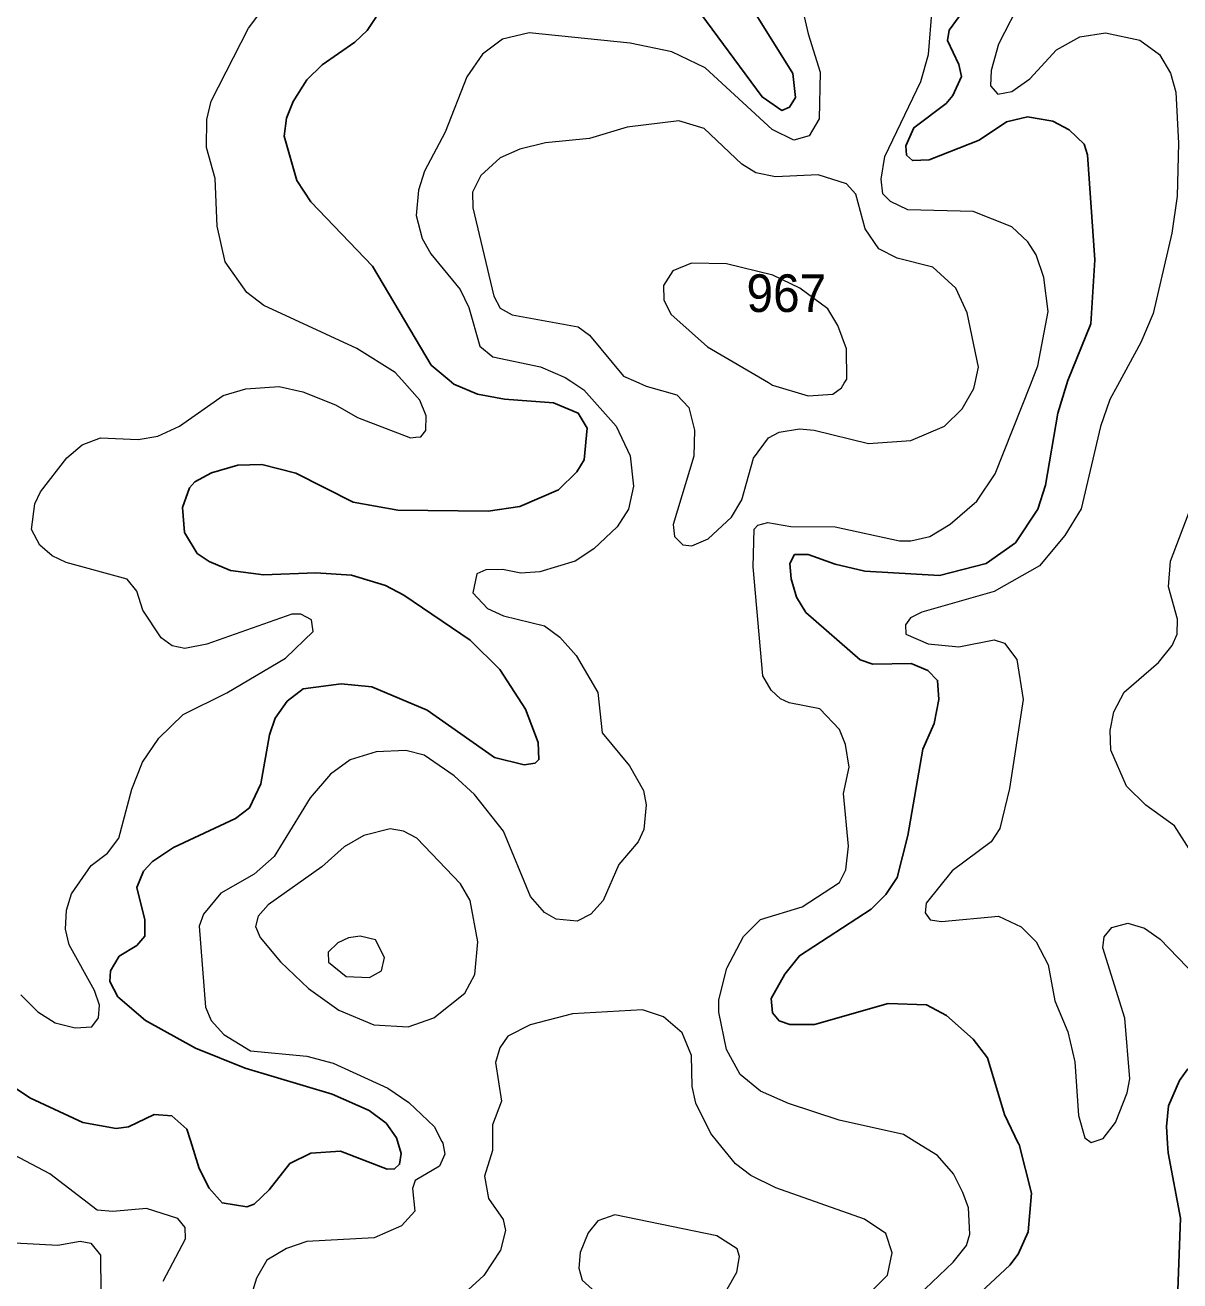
# Model space of a CAD drawing. Extents: x 473.9 to 500, y 7733.1 to 7760.8.
# Drawn here: x 476.742 to 479.198, y 7746.08 to 7748.751 of the extents above; entities that cross this region are included whole.
import ezdxf

# ---------------------------------------------------------------- set-up
doc = ezdxf.new("R2010")
doc.units = 0
doc.header["$LTSCALE"] = 0.032
doc.layers.add('1', color=7, linetype='Continuous', lineweight=25)
doc.layers.add('2', color=7, linetype='Continuous', lineweight=13)
doc.layers.add('21', color=7, linetype='Continuous')

msp = doc.modelspace()

# ---------------------------------------------------------------- linework, layer by layer
at = {"layer": '1'}
for points in [[(477.5474, 7747.5383), (477.5084, 7747.5589), (477.4357, 7747.5809), (477.3604, 7747.5858), (477.2492, 7747.5818), (477.1784, 7747.5908), (477.1331, 7747.61), (477.1081, 7747.6274), (477.0809, 7747.6718), (477.0769, 7747.7251), (477.0912, 7747.7667), (477.103, 7747.7795), (477.1386, 7747.799), (477.1942, 7747.8152), (477.2453, 7747.8166), (477.3178, 7747.7977), (477.4393, 7747.736), (477.5349, 7747.7193), (477.7267, 7747.7169), (477.7937, 7747.7271), (477.876, 7747.7625), (477.9153, 7747.8008), (477.9312, 7747.8267), (477.9375, 7747.8938), (477.9184, 7747.9259), (477.8653, 7747.9478), (477.7612, 7747.9556), (477.7043, 7747.9663), (477.6534, 7747.9876), (477.6436, 7747.9958), (477.6053, 7748.0281), (477.4807, 7748.2382), (477.3496, 7748.3751), (477.3197, 7748.4205), (477.293, 7748.5147), (477.2979, 7748.5535), (477.3118, 7748.5889), (477.3413, 7748.6347), (477.3739, 7748.6669), (477.4432, 7748.7147), (477.4697, 7748.7397), (477.5418, 7748.8495)], [(478.1666, 7748.7915), (478.3092, 7748.5985), (478.3511, 7748.5697), (478.3674, 7748.5764), (478.3805, 7748.5972), (478.3749, 7748.6481), (478.2948, 7748.7769)], [(478.7282, 7748.7695), (478.7069, 7748.7402), (478.7035, 7748.7189), (478.7279, 7748.6674), (478.7333, 7748.6423), (478.7148, 7748.6017), (478.7006, 7748.5846), (478.6322, 7748.5329), (478.6149, 7748.4942), (478.6165, 7748.4744), (478.6289, 7748.4632), (478.6646, 7748.4645), (478.7706, 7748.5065), (478.829, 7748.5457), (478.8736, 7748.556), (478.9273, 7748.5467), (478.9621, 7748.5287), (478.9942, 7748.498), (479.0011, 7748.475), (479.0171, 7748.2516), (479.0084, 7748.1161), (478.9598, 7747.9955), (478.9568, 7747.9858), (478.9383, 7747.9256), (478.9118, 7747.7724), (478.896, 7747.7215), (478.8482, 7747.65), (478.7858, 7747.6056), (478.6864, 7747.5806), (478.5279, 7747.5893), (478.4648, 7747.6041), (478.4073, 7747.6252), (478.3783, 7747.6248), (478.3686, 7747.6057), (478.3709, 7747.5729), (478.3821, 7747.5344), (478.4021, 7747.5017), (478.5181, 7747.401), (478.5451, 7747.3916), (478.6263, 7747.3931), (478.6615, 7747.3781), (478.6825, 7747.3572), (478.6851, 7747.3166), (478.6751, 7747.2655), (478.6512, 7747.2105), (478.6195, 7747.0275), (478.5967, 7746.9379), (478.5721, 7746.9019), (478.5409, 7746.8707), (478.3885, 7746.7713), (478.3575, 7746.7324), (478.3288, 7746.6801), (478.3311, 7746.6497), (478.3456, 7746.6329), (478.3683, 7746.625), (478.4208, 7746.6248), (478.5777, 7746.6696), (478.6587, 7746.6667), (478.7015, 7746.6439), (478.7583, 7746.5936), (478.7883, 7746.5542), (478.8245, 7746.4339), (478.8542, 7746.3726), (478.8557, 7746.3695), (478.882, 7746.2663), (478.8754, 7746.184), (478.8541, 7746.1364), (478.8362, 7746.1128), (478.7229, 7746.0072)], [(476.6946, 7746.5074), (476.7534, 7746.468), (476.8644, 7746.4166), (476.9354, 7746.404), (476.9621, 7746.4072), (477.0161, 7746.4335), (477.0539, 7746.431), (477.0859, 7746.4026), (477.0937, 7746.378), (477.1122, 7746.319), (477.1331, 7746.277), (477.161, 7746.2457), (477.2138, 7746.2374), (477.2287, 7746.2425), (477.2613, 7746.2731), (477.3052, 7746.3295), (477.3495, 7746.351), (477.4126, 7746.3557), (477.512, 7746.3171), (477.5278, 7746.3177), (477.5382, 7746.3278), (477.5417, 7746.3508), (477.5339, 7746.3766), (477.5318, 7746.3836), (477.5096, 7746.4151), (477.4735, 7746.4424), (477.3952, 7746.4766), (477.2096, 7746.5323), (477.1044, 7746.5748), (476.9981, 7746.6333), (476.939, 7746.6842), (476.9224, 7746.7162), (476.9233, 7746.7395), (476.9421, 7746.7701), (476.9792, 7746.7928), (476.9965, 7746.8133), (476.9965, 7746.8474), (476.9792, 7746.9162), (476.9937, 7746.9511), (477.0131, 7746.9718), (477.0573, 7747.0017), (477.1897, 7747.0632), (477.2189, 7747.0862), (477.2435, 7747.1371), (477.2616, 7747.2412), (477.274, 7747.2765), (477.2995, 7747.3129), (477.3332, 7747.3391), (477.4142, 7747.3502), (477.4791, 7747.3436), (477.5971, 7747.2936), (477.7401, 7747.1933), (477.8033, 7747.1775), (477.8268, 7747.1811), (477.8345, 7747.1886), (477.833, 7747.225), (477.8063, 7747.2963), (477.7512, 7747.3804), (477.6883, 7747.4428), (477.5474, 7747.5383)], [(479.2145, 7745.9562), (479.1935, 7746.06), (479.1988, 7746.2132), (479.1727, 7746.3519), (479.1714, 7746.3717), (479.1691, 7746.4081), (479.1733, 7746.4521), (479.1969, 7746.5058), (479.215, 7746.5311)]]:
    msp.add_lwpolyline(points, dxfattribs=at)
at = {"layer": '2'}
for points in [[(478.3789, 7748.8562), (478.407, 7748.7324), (478.4327, 7748.6514), (478.4304, 7748.5522), (478.4091, 7748.5155), (478.3767, 7748.5063), (478.3307, 7748.529), (478.1883, 7748.6607), (478.1175, 7748.6945), (478.0286, 7748.713), (477.8142, 7748.7347), (477.7573, 7748.7217), (477.7143, 7748.6893), (477.6812, 7748.6412), (477.6352, 7748.5237), (477.5914, 7748.4406), (477.5787, 7748.4005), (477.5733, 7748.3459), (477.5861, 7748.297)], [(477.031, 7747.448), (476.9923, 7747.5065), (476.9792, 7747.5467), (476.9592, 7747.5723), (476.829, 7747.6078), (476.7998, 7747.622), (476.7729, 7747.6451), (476.7556, 7747.6785), (476.7625, 7747.7327), (476.7748, 7747.758), (476.8304, 7747.8309), (476.8631, 7747.8583), (476.9024, 7747.8729), (476.9822, 7747.8697), (477.0239, 7747.877), (477.0706, 7747.8979), (477.1631, 7747.9632), (477.2112, 7747.9774), (477.2824, 7747.9821), (477.3328, 7747.9709), (477.4019, 7747.9435), (477.4485, 7747.9165), (477.5617, 7747.8735), (477.5726, 7747.8746), (477.5836, 7747.8756), (477.5941, 7747.8888), (477.5949, 7747.9197), (477.5815, 7747.9535), (477.5428, 7747.9966), (477.529, 7748.0119), (477.4471, 7748.0633), (477.2495, 7748.155), (477.2137, 7748.1827), (477.1675, 7748.2478), (477.1504, 7748.3233), (477.1464, 7748.4252), (477.1279, 7748.4906), (477.1286, 7748.5506), (477.1378, 7748.5898), (477.2168, 7748.7445), (477.2665, 7748.8115)], [(478.7166, 7746.3075), (478.682, 7746.3461), (478.6383, 7746.3733), (478.6097, 7746.3911), (478.473, 7746.4216), (478.3652, 7746.457), (478.3057, 7746.4835), (478.2623, 7746.5189), (478.2334, 7746.572), (478.2173, 7746.6516), (478.2173, 7746.6773), (478.2342, 7746.7449), (478.2695, 7746.8124), (478.3057, 7746.8486), (478.3942, 7746.8751), (478.4738, 7746.9274), (478.4874, 7746.9539), (478.4931, 7747.0046), (478.4826, 7747.1163), (478.4947, 7747.1726), (478.4866, 7747.2208), (478.4738, 7747.253), (478.432, 7747.2964), (478.3668, 7747.3093), (478.3483, 7747.3181), (478.3282, 7747.3366), (478.3105, 7747.3672), (478.2904, 7747.5987), (478.2921, 7747.6791), (478.3001, 7747.6872), (478.3218, 7747.6928), (478.3701, 7747.6847), (478.4649, 7747.6839), (478.6016, 7747.6542), (478.6257, 7747.6542), (478.6659, 7747.663), (478.7094, 7747.6896), (478.7656, 7747.7386), (478.805, 7747.7965), (478.88, 7747.9863), (478.8959, 7748.0265), (478.9176, 7748.1422), (478.9087, 7748.2146), (478.8919, 7748.2628), (478.8742, 7748.2902), (478.8404, 7748.3223), (478.7584, 7748.3545), (478.6193, 7748.3585), (478.5823, 7748.3762), (478.5662, 7748.3923), (478.5622, 7748.4236), (478.5702, 7748.4719), (478.6466, 7748.6311), (478.6635, 7748.689), (478.6708, 7748.7855)], [(478.8627, 7748.8095), (478.8117, 7748.7109), (478.7966, 7748.655), (478.7952, 7748.6224), (478.8107, 7748.6046), (478.8405, 7748.6099), (478.8785, 7748.6371), (478.9353, 7748.6985), (478.9852, 7748.7267), (479.0395, 7748.7347), (479.1124, 7748.7196), (479.1542, 7748.6888)], [(479.1542, 7748.6888), (479.1777, 7748.649), (479.1891, 7748.609), (479.195, 7748.5002), (479.1918, 7748.3872), (479.181, 7748.3089), (479.1412, 7748.1379), (479.115, 7748.0757), (479.0652, 7747.9849), (479.0489, 7747.9551), (479.0291, 7747.8972), (478.9876, 7747.7219), (478.9532, 7747.6651), (478.8991, 7747.6008), (478.803, 7747.5461), (478.6491, 7747.5024), (478.6246, 7747.4905), (478.6139, 7747.4755), (478.615, 7747.4558), (478.6626, 7747.4347), (478.728, 7747.4283), (478.8025, 7747.4435), (478.8245, 7747.4365), (478.851, 7747.4019), (478.8644, 7747.3162), (478.8354, 7747.127), (478.8147, 7747.0424), (478.7965, 7747.0137), (478.7137, 7746.9518), (478.6579, 7746.8835), (478.6562, 7746.8627), (478.6668, 7746.8481), (478.6906, 7746.8445), (478.8122, 7746.8556), (478.8605, 7746.8327), (478.8918, 7746.801), (478.9176, 7746.7523), (478.9318, 7746.6751), (478.9593, 7746.6097), (478.9746, 7746.5454), (478.9825, 7746.4318), (478.9954, 7746.3837), (479.009, 7746.3743), (479.0346, 7746.3826), (479.0609, 7746.4166), (479.0856, 7746.4795), (479.091, 7746.5095), (479.0807, 7746.6386), (479.0342, 7746.7882), (479.0366, 7746.8113), (479.0529, 7746.8313), (479.0872, 7746.8405), (479.1225, 7746.83), (479.1555, 7746.8067), (479.2316, 7746.7276)], [(477.5861, 7748.297), (477.605, 7748.265), (477.6672, 7748.1889), (477.6857, 7748.1502), (477.7093, 7748.0686), (477.7369, 7748.0456), (477.8381, 7748.0245), (477.8903, 7748.0016), (477.9022, 7747.9938), (477.9301, 7747.9756), (477.9992, 7747.8984), (478.029, 7747.835), (478.0355, 7747.7702), (478.0253, 7747.7214), (478.0013, 7747.6842), (477.9515, 7747.6369), (477.9115, 7747.6108), (477.8367, 7747.588), (477.7965, 7747.585), (477.7573, 7747.593), (477.7219, 7747.5921), (477.7029, 7747.5836), (477.6941, 7747.5434), (477.725, 7747.5104), (477.7591, 7747.4946), (477.8464, 7747.4729), (477.8788, 7747.4491), (477.914, 7747.4104), (477.9598, 7747.3317), (477.9692, 7747.2455), (478.0271, 7747.1754), (478.0571, 7747.1227), (478.0628, 7747.0921), (478.0577, 7747.0398), (478.046, 7747.0139), (478.0043, 7746.9654), (477.971, 7746.8888), (477.9451, 7746.8601), (477.9159, 7746.8448), (477.8714, 7746.8489), (477.8464, 7746.8635), (477.8169, 7746.8976), (477.7591, 7747.0367), (477.6977, 7747.1147), (477.6545, 7747.1541), (477.5906, 7747.198), (477.5515, 7747.2079), (477.4883, 7747.2053), (477.4331, 7747.188), (477.3912, 7747.1578), (477.3484, 7747.1071), (477.2719, 7746.9825), (477.2294, 7746.9447), (477.1584, 7746.9048), (477.1212, 7746.8598), (477.1121, 7746.8342), (477.1256, 7746.6618), (477.1374, 7746.6337), (477.1644, 7746.6037), (477.2213, 7746.5692), (477.3408, 7746.5574), (477.3971, 7746.5429), (477.513, 7746.4899), (477.5579, 7746.4593), (477.6119, 7746.4078), (477.6279, 7746.3763), (477.63, 7746.3723), (477.6342, 7746.3492), (477.6231, 7746.3236), (477.5718, 7746.2931), (477.5659, 7746.2758), (477.571, 7746.2278), (477.5422, 7746.1967), (477.4845, 7746.1714), (477.3409, 7746.1633), (477.2981, 7746.1486), (477.256, 7746.1236), (477.2342, 7746.0855), (477.2079, 7745.9997)], [(479.2174, 7746.9988), (479.1864, 7747.0476), (479.1254, 7747.0917), (479.0843, 7747.1319), (479.0506, 7747.2084), (479.0494, 7747.2509), (479.0572, 7747.2905), (479.0796, 7747.332), (479.1522, 7747.3955), (479.1812, 7747.4315), (479.1917, 7747.4556), (479.1926, 7747.4872), (479.1736, 7747.5564), (479.1779, 7747.6105), (479.2238, 7747.7322)], [(476.7327, 7746.6882), (476.7693, 7746.6522), (476.8056, 7746.6289), (476.8486, 7746.6181), (476.8841, 7746.6203), (476.8981, 7746.6389), (476.9001, 7746.6665), (476.8895, 7746.6972), (476.8356, 7746.7948), (476.8279, 7746.8279), (476.8302, 7746.868), (476.8404, 7746.9034), (476.8821, 7746.963), (476.9168, 7746.9898), (476.9415, 7747.0218), (476.9687, 7747.1259), (476.9917, 7747.1831), (477.026, 7747.2342), (477.0783, 7747.2847), (477.1709, 7747.3304), (477.2955, 7747.4044), (477.3547, 7747.4611), (477.3511, 7747.486), (477.3284, 7747.4978), (477.3093, 7747.4981), (477.1281, 7747.4345), (477.0814, 7747.425), (477.0545, 7747.4307), (477.031, 7747.448)], [(478.4036, 7745.9208), (478.5758, 7746.092), (478.5862, 7746.1391), (478.5725, 7746.1805), (478.5271, 7746.211), (478.3385, 7746.2774), (478.2853, 7746.3039), (478.2524, 7746.3286), (478.215, 7746.3746), (478.2, 7746.393), (478.1682, 7746.4574), (478.1602, 7746.4929), (478.1592, 7746.5588), (478.1391, 7746.6072), (478.0993, 7746.6413), (478.055, 7746.6564), (477.9058, 7746.6476), (477.8163, 7746.6247), (477.7687, 7746.6), (477.7515, 7746.5754), (477.7422, 7746.5444), (477.7551, 7746.4619), (477.7356, 7746.4114), (477.7356, 7746.376), (477.7356, 7746.3573), (477.7188, 7746.3021), (477.7276, 7746.2548), (477.7583, 7746.2104), (477.7637, 7746.1868), (477.7526, 7746.1451), (477.7178, 7746.0913), (477.6839, 7746.0607)], [(477.0353, 7746.0788), (477.0827, 7746.1691), (477.0826, 7746.1933), (477.0667, 7746.212), (476.9999, 7746.2333), (476.9287, 7746.2271), (476.8955, 7746.2304), (476.7944, 7746.3077), (476.6659, 7746.3747), (476.6335, 7746.3749), (476.5916, 7746.3532), (476.5683, 7746.3222), (476.5534, 7746.2848), (476.5482, 7746.2244), (476.5568, 7746.1697), (476.5697, 7746.1485), (476.6329, 7746.1274), (476.6589, 7746.1323), (476.7201, 7746.1604), (476.8117, 7746.1556), (476.859, 7746.1644), (476.8817, 7746.1597), (476.9026, 7746.1343), (476.9028, 7746.0554)], [(478.641, 7746.0486), (478.7158, 7746.1193), (478.7439, 7746.1547), (478.7512, 7746.1788), (478.7479, 7746.2351), (478.7359, 7746.2673), (478.7166, 7746.3075)]]:
    msp.add_lwpolyline(points, dxfattribs=at)
for points in [[(478.5355, 7747.8613), (478.6255, 7747.8676), (478.6975, 7747.8978), (478.7345, 7747.9351), (478.7598, 7747.9782), (478.7617, 7747.9872), (478.7696, 7748.0237), (478.7454, 7748.1389), (478.7213, 7748.192), (478.6721, 7748.2362), (478.5963, 7748.2558), (478.5574, 7748.2755), (478.5284, 7748.3176), (478.5088, 7748.3919), (478.489, 7748.4133), (478.4286, 7748.4326), (478.338, 7748.4286), (478.2962, 7748.4373), (478.266, 7748.4554), (478.1862, 7748.5316), (478.1325, 7748.5475), (478.0221, 7748.5343), (477.9421, 7748.51), (477.8487, 7748.5007), (477.7937, 7748.4874), (477.7521, 7748.4692), (477.7108, 7748.4316), (477.6934, 7748.3956), (477.6938, 7748.3625), (477.7387, 7748.1749), (477.7525, 7748.1494), (477.778, 7748.1349), (477.9181, 7748.1092), (477.9422, 7748.0915), (478.0142, 7748.0047), (478.0409, 7747.9928), (478.0624, 7747.9832), (478.1277, 7747.9649), (478.1536, 7747.938), (478.1657, 7747.8897), (478.1642, 7747.834), (478.12, 7747.6887), (478.1233, 7747.6633), (478.1408, 7747.6458), (478.1597, 7747.6438), (478.1945, 7747.6584), (478.2442, 7747.7041), (478.266, 7747.7412), (478.291, 7747.8297), (478.3227, 7747.8733), (478.3453, 7747.8854), (478.3887, 7747.8922), (478.4198, 7747.8897)], [(478.47, 7748.1125), (478.4489, 7748.1475), (478.3893, 7748.1916), (478.3322, 7748.2192), (478.2333, 7748.2434), (478.1588, 7748.2449), (478.1196, 7748.2285), (478.0998, 7748.197), (478.1006, 7748.1668), (478.1152, 7748.1365), (478.1928, 7748.0666), (478.3228, 7747.9906), (478.3315, 7747.9855), (478.4072, 7747.9625), (478.46, 7747.9662), (478.4783, 7747.9796), (478.4841, 7747.9894), (478.4893, 7747.9982), (478.489, 7748.0628)], [(477.5565, 7746.6202), (477.6108, 7746.6394), (477.6769, 7746.6918), (477.6981, 7746.7313), (477.705, 7746.801), (477.6881, 7746.8887), (477.6678, 7746.9246), (477.5752, 7747.0217), (477.5463, 7747.0364), (477.5182, 7747.0414), (477.4623, 7747.0273), (477.4204, 7747.0033), (477.3729, 7746.9604), (477.2588, 7746.8798), (477.2379, 7746.8555), (477.2317, 7746.8334), (477.242, 7746.8099), (477.2853, 7746.7584), (477.3449, 7746.7017), (477.4089, 7746.6553), (477.4836, 7746.6246)], [(477.4742, 7746.725), (477.4995, 7746.739), (477.5063, 7746.7678), (477.4871, 7746.805), (477.4545, 7746.8131), (477.4294, 7746.8098), (477.4067, 7746.7986), (477.3862, 7746.7788), (477.3872, 7746.7578), (477.4246, 7746.7272)], [(478.1127, 7746.0156), (478.179, 7746.0288), (478.2349, 7746.0622), (478.2556, 7746.0979), (478.2615, 7746.1312), (478.2559, 7746.1481), (478.2127, 7746.1756), (477.9964, 7746.2204), (477.9598, 7746.2072), (477.9396, 7746.1815), (477.9226, 7746.1399), (477.9198, 7746.1064), (477.9263, 7746.0813), (477.9686, 7746.0437), (477.9992, 7746.0284), (478.0506, 7746.0148)]]:
    msp.add_lwpolyline(points, close=True, dxfattribs=at)

# ---------------------------------------------------------------- texts
at = {"layer": '21', "width": 0.95}
msp.add_text('967', height=0.08, dxfattribs=at).set_placement((478.2761, 7748.141))

doc.saveas('drawing.dxf')
